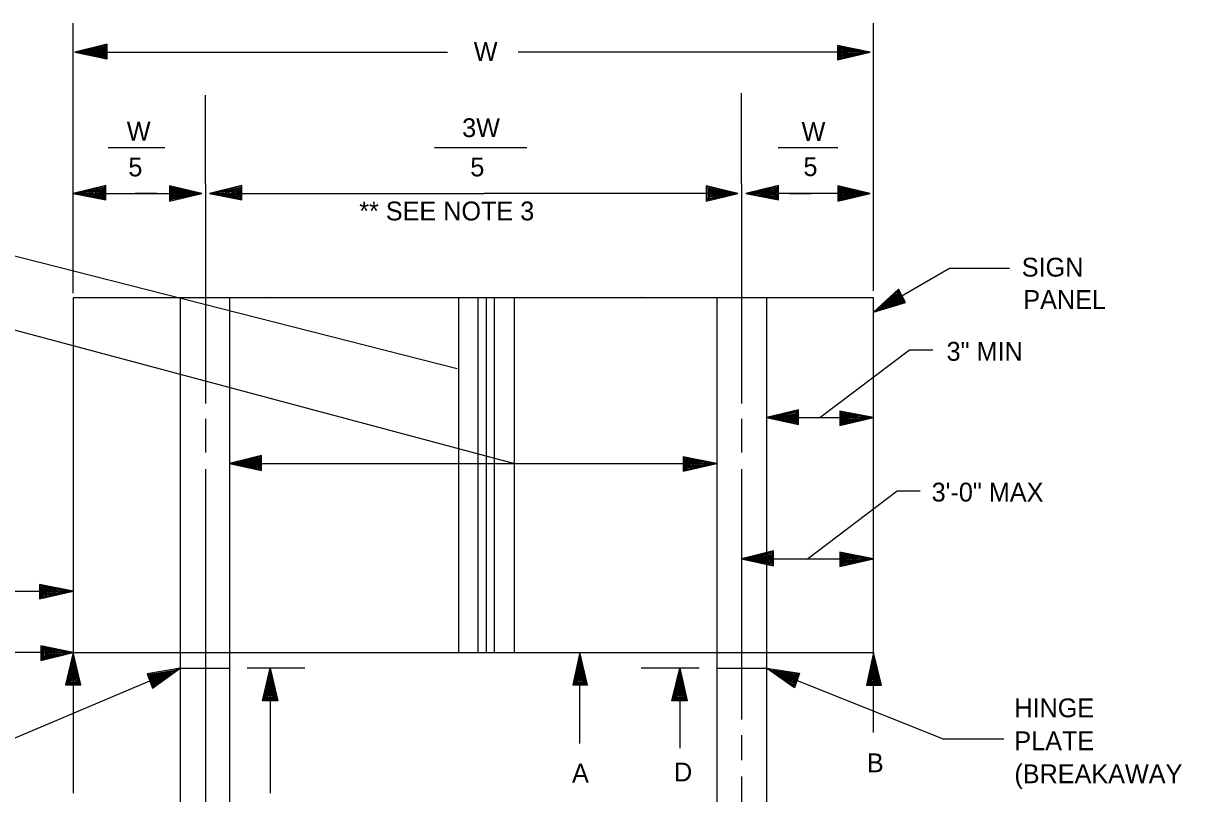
# Model space of a CAD drawing. Extents: x 139.2 to 146.5, y 202.4 to 212.6.
# Drawn here: x 142.714 to 146.404, y 210.118 to 212.573 of the extents above; entities that cross this region are included whole.
import ezdxf

# ---------------------------------------------------------------- set-up
doc = ezdxf.new("R2010")
doc.units = 0
for name, color, linetype in [('DETL-DIMS', 7, 'Continuous'), ('DETL-NOTE', 7, 'Continuous'), ('TTLB-TEXT', 7, 'Continuous')]:
    doc.layers.add(name, color=color, linetype=linetype)

msp = doc.modelspace()

# ---------------------------------------------------------------- linework, layer by layer
at = {"layer": 'DETL-DIMS'}
for p, q in [((142.873, 211.713), (142.873, 212.5728)), ((145.422, 211.7206), (145.422, 212.5728)), ((142.878, 212.4808), (144.065, 212.4808)), ((145.411, 212.4808), (144.29, 212.4808)), ((143.295, 212.0608), (143.295, 212.3438)), ((145.002, 212.0608), (145.002, 212.3498)), ((142.873, 212.0308), (143.283, 212.0308)), ((143.14, 212.0308), (143.071, 212.0308)), ((143.295, 212.0608), (143.295, 211.361)), ((143.307, 212.0308), (144.182, 212.0308)), ((144.99, 212.0308), (144.182, 212.0308)), ((145.002, 212.0608), (145.002, 211.361)), ((145.411, 212.0308), (145.015, 212.0308)), ((145.155, 212.0308), (145.224, 212.0308)), ((145.422, 211.6521), (145.6644, 211.7924)), ((145.6644, 211.7924), (145.8554, 211.7924)), ((145.2515, 211.3164), (145.5364, 211.5328)), ((145.5364, 211.5328), (145.6105, 211.5328)), ((143.295, 211.313), (143.295, 211.205)), ((145.002, 211.313), (145.002, 211.205)), ((145.081, 211.3164), (145.422, 211.3164)), ((143.295, 211.152), (143.295, 209.857)), ((143.371, 211.1706), (144.923, 211.1706)), ((145.002, 211.152), (145.002, 210.355)), ((145.212, 210.8669), (145.4969, 211.0833)), ((145.4969, 211.0833), (145.571, 211.0833)), ((145.002, 210.8669), (145.422, 210.8669)), ((140.875, 210.764), (142.873, 210.764)), ((142.873, 210.568), (140.273, 210.568)), ((142.873, 210.568), (142.873, 210.12)), ((144.4864, 210.2787), (144.4864, 210.568)), ((145.422, 210.314), (145.422, 210.568)), ((143.214, 210.518), (142.5028, 210.2173)), ((143.6114, 210.518), (143.4274, 210.518)), ((143.5008, 210.518), (143.5008, 210.12)), ((144.8664, 210.518), (144.6824, 210.518)), ((144.8049, 210.518), (144.8049, 210.2637)), ((145.081, 210.518), (145.6457, 210.2927)), ((145.002, 210.305), (145.002, 210.225)), ((145.8367, 210.2927), (145.6457, 210.2927)), ((145.002, 210.173), (145.002, 209.805))]:
    msp.add_line(p, q, dxfattribs=at)
for points in [[(142.982, 212.5058), (142.878, 212.4808), (142.982, 212.4588), (142.982, 212.5058)], [(142.978, 212.5018), (142.889, 212.4808), (142.978, 212.4588), (142.978, 212.5018)], [(142.977, 212.4978), (142.898, 212.4808), (142.977, 212.4628), (142.977, 212.4978)], [(142.975, 212.4968), (142.908, 212.4808), (142.975, 212.4668), (142.975, 212.4968)], [(142.972, 212.4928), (142.919, 212.4808), (142.972, 212.4688), (142.972, 212.4928)], [(142.971, 212.4918), (142.927, 212.4808), (142.971, 212.4688), (142.971, 212.4918)], [(142.968, 212.4878), (142.938, 212.4808), (142.968, 212.4728), (142.968, 212.4878)], [(142.966, 212.4838), (142.947, 212.4808), (142.966, 212.4768), (142.966, 212.4838)], [(142.965, 212.4828), (142.957, 212.4808), (142.965, 212.4788), (142.965, 212.4828)], [(145.307, 212.4558), (145.411, 212.4808), (145.307, 212.5018), (145.307, 212.4558)], [(145.308, 212.4588), (145.401, 212.4808), (145.308, 212.5008), (145.308, 212.4588)], [(145.313, 212.4608), (145.39, 212.4808), (145.313, 212.4968), (145.313, 212.4608)], [(145.315, 212.4628), (145.38, 212.4788), (145.315, 212.4958), (145.315, 212.4628)], [(145.316, 212.4668), (145.371, 212.4788), (145.316, 212.4918), (145.316, 212.4668)], [(145.318, 212.4688), (145.36, 212.4788), (145.318, 212.4878), (145.318, 212.4688)], [(145.319, 212.4718), (145.352, 212.4788), (145.319, 212.4858), (145.319, 212.4718)], [(145.323, 212.4758), (145.341, 212.4788), (145.323, 212.4838), (145.323, 212.4758)], [(145.325, 212.4768), (145.331, 212.4788), (145.325, 212.4808), (145.325, 212.4768)], [(144.0957, 211.472), (141.6601, 212.0915), (141.5263, 212.0915)], [(142.977, 212.0558), (142.873, 212.0308), (142.977, 212.0098), (142.977, 212.0558)], [(142.975, 212.0548), (142.883, 212.0308), (142.975, 212.0118), (142.975, 212.0548)], [(142.972, 212.0498), (142.894, 212.0308), (142.972, 212.0148), (142.972, 212.0498)], [(142.971, 212.0488), (142.905, 212.0328), (142.971, 212.0158), (142.971, 212.0488)], [(142.968, 212.0448), (142.913, 212.0328), (142.968, 212.0198), (142.968, 212.0448)], [(142.966, 212.0408), (142.923, 212.0328), (142.966, 212.0238), (142.966, 212.0408)], [(142.965, 212.0398), (142.932, 212.0328), (142.965, 212.0248), (142.965, 212.0398)], [(142.961, 212.0358), (142.943, 212.0328), (142.961, 212.0278), (142.961, 212.0358)], [(142.958, 212.0348), (142.953, 212.0328), (142.958, 212.0308), (142.958, 212.0348)], [(143.18, 212.0058), (143.283, 212.0308), (143.18, 212.0548), (143.18, 212.0058)], [(143.18, 212.0098), (143.273, 212.0308), (143.18, 212.0528), (143.18, 212.0098)], [(143.183, 212.0138), (143.263, 212.0308), (143.183, 212.0488), (143.183, 212.0138)], [(143.186, 212.0148), (143.252, 212.0308), (143.186, 212.0448), (143.186, 212.0148)], [(143.188, 212.0188), (143.243, 212.0308), (143.188, 212.0438), (143.188, 212.0188)], [(143.19, 212.0198), (143.232, 212.0308), (143.19, 212.0408), (143.19, 212.0198)], [(143.191, 212.0238), (143.223, 212.0308), (143.191, 212.0388), (143.191, 212.0238)], [(143.194, 212.0278), (143.213, 212.0308), (143.194, 212.0348), (143.194, 212.0278)], [(143.197, 212.0298), (143.202, 212.0308), (143.197, 212.0328), (143.197, 212.0298)], [(143.41, 212.0558), (143.307, 212.0308), (143.41, 212.0098), (143.41, 212.0558)], [(143.41, 212.0548), (143.316, 212.0308), (143.41, 212.0118), (143.41, 212.0548)], [(143.408, 212.0498), (143.327, 212.0308), (143.408, 212.0148), (143.408, 212.0498)], [(143.405, 212.0488), (143.336, 212.0328), (143.405, 212.0158), (143.405, 212.0488)], [(143.401, 212.0448), (143.347, 212.0328), (143.401, 212.0198), (143.401, 212.0448)], [(143.4, 212.0408), (143.357, 212.0328), (143.4, 212.0238), (143.4, 212.0408)], [(143.396, 212.0398), (143.366, 212.0328), (143.396, 212.0248), (143.396, 212.0398)], [(143.395, 212.0358), (143.377, 212.0328), (143.395, 212.0278), (143.395, 212.0358)], [(143.394, 212.0348), (143.385, 212.0328), (143.394, 212.0308), (143.394, 212.0348)], [(144.889, 212.0058), (144.99, 212.0308), (144.889, 212.0548), (144.889, 212.0058)], [(144.89, 212.0098), (144.982, 212.0308), (144.89, 212.0528), (144.89, 212.0098)], [(144.89, 212.0138), (144.971, 212.0308), (144.89, 212.0488), (144.89, 212.0138)], [(144.895, 212.0148), (144.963, 212.0308), (144.895, 212.0448), (144.895, 212.0148)], [(144.896, 212.0188), (144.951, 212.0308), (144.896, 212.0438), (144.896, 212.0188)], [(144.899, 212.0198), (144.94, 212.0308), (144.899, 212.0408), (144.899, 212.0198)], [(144.901, 212.0238), (144.932, 212.0308), (144.901, 212.0388), (144.901, 212.0238)], [(144.905, 212.0278), (144.921, 212.0308), (144.905, 212.0348), (144.905, 212.0278)], [(144.905, 212.0298), (144.913, 212.0308), (144.905, 212.0328), (144.905, 212.0298)], [(145.12, 212.0558), (145.015, 212.0308), (145.12, 212.0098), (145.12, 212.0558)], [(145.118, 212.0548), (145.026, 212.0308), (145.118, 212.0118), (145.118, 212.0548)], [(145.115, 212.0498), (145.036, 212.0308), (145.115, 212.0148), (145.115, 212.0498)], [(145.113, 212.0488), (145.047, 212.0328), (145.113, 212.0158), (145.113, 212.0488)], [(145.11, 212.0448), (145.056, 212.0328), (145.11, 212.0198), (145.11, 212.0448)], [(145.11, 212.0408), (145.066, 212.0328), (145.11, 212.0238), (145.11, 212.0408)], [(145.107, 212.0398), (145.076, 212.0328), (145.107, 212.0248), (145.107, 212.0398)], [(145.103, 212.0358), (145.086, 212.0328), (145.103, 212.0278), (145.103, 212.0358)], [(145.102, 212.0348), (145.097, 212.0328), (145.102, 212.0308), (145.102, 212.0348)], [(145.308, 212.0058), (145.411, 212.0308), (145.308, 212.0548), (145.308, 212.0058)], [(145.311, 212.0098), (145.402, 212.0308), (145.311, 212.0528), (145.311, 212.0098)], [(145.313, 212.0138), (145.391, 212.0308), (145.313, 212.0488), (145.313, 212.0138)], [(145.316, 212.0148), (145.383, 212.0308), (145.316, 212.0448), (145.316, 212.0148)], [(145.318, 212.0188), (145.373, 212.0308), (145.318, 212.0438), (145.318, 212.0188)], [(145.319, 212.0198), (145.363, 212.0308), (145.319, 212.0408), (145.319, 212.0198)], [(145.323, 212.0238), (145.353, 212.0308), (145.323, 212.0388), (145.323, 212.0238)], [(145.325, 212.0278), (145.343, 212.0308), (145.325, 212.0348), (145.325, 212.0278)], [(145.327, 212.0298), (145.333, 212.0308), (145.327, 212.0328), (145.327, 212.0298)], [(144.2793, 211.1696), (141.7634, 211.8414), (141.6646, 211.8414)], [(145.5013, 211.7261), (145.422, 211.6521), (145.5242, 211.6829), (145.5013, 211.7261)], [(145.5004, 211.7221), (145.431, 211.6587), (145.5206, 211.6848), (145.5004, 211.7221)], [(145.5, 211.7212), (145.4391, 211.6636), (145.5171, 211.6866), (145.5, 211.7212)], [(145.499, 211.7171), (145.4498, 211.6693), (145.5153, 211.6875), (145.499, 211.7171)], [(145.4994, 211.7113), (145.4575, 211.6732), (145.5117, 211.6893), (145.4994, 211.7113)], [(145.4985, 211.7095), (145.4656, 211.6781), (145.5082, 211.6911), (145.4985, 211.7095)], [(145.498, 211.7064), (145.4741, 211.6838), (145.5046, 211.6929), (145.498, 211.7064)], [(145.4966, 211.7015), (145.4831, 211.6882), (145.5015, 211.6934), (145.4966, 211.7015)], [(145.4948, 211.698), (145.4912, 211.6931), (145.4979, 211.6952), (145.4948, 211.698)], [(145.183, 211.3414), (145.081, 211.3164), (145.183, 211.2944), (145.183, 211.3414)], [(145.182, 211.3384), (145.093, 211.3164), (145.182, 211.2954), (145.182, 211.3384)], [(145.181, 211.3344), (145.099, 211.3164), (145.181, 211.2994), (145.181, 211.3344)], [(145.178, 211.3334), (145.11, 211.3164), (145.178, 211.3034), (145.178, 211.3334)], [(145.177, 211.3284), (145.119, 211.3164), (145.177, 211.3044), (145.177, 211.3284)], [(145.173, 211.3284), (145.13, 211.3164), (145.173, 211.3054), (145.173, 211.3284)], [(145.315, 211.2914), (145.422, 211.3164), (145.315, 211.3374), (145.315, 211.2914)], [(145.319, 211.2924), (145.411, 211.3164), (145.319, 211.3344), (145.319, 211.2924)], [(145.323, 211.2964), (145.399, 211.3164), (145.323, 211.3304), (145.323, 211.2964)], [(145.324, 211.2974), (145.389, 211.3134), (145.324, 211.3294), (145.324, 211.2974)], [(145.324, 211.3014), (145.38, 211.3134), (145.324, 211.3264), (145.324, 211.3014)], [(145.172, 211.3244), (145.141, 211.3164), (145.172, 211.3094), (145.172, 211.3244)], [(145.168, 211.3204), (145.152, 211.3164), (145.168, 211.3134), (145.168, 211.3204)], [(145.166, 211.3184), (145.161, 211.3164), (145.166, 211.3144), (145.166, 211.3184)], [(145.328, 211.3054), (145.369, 211.3134), (145.328, 211.3224), (145.328, 211.3054)], [(145.329, 211.3074), (145.36, 211.3134), (145.329, 211.3204), (145.329, 211.3074)], [(145.333, 211.3094), (145.349, 211.3134), (145.333, 211.3184), (145.333, 211.3094)], [(145.334, 211.3124), (145.339, 211.3134), (145.334, 211.3164), (145.334, 211.3124)], [(143.473, 211.1956), (143.371, 211.1706), (143.473, 211.1486), (143.473, 211.1956)], [(143.472, 211.1926), (143.383, 211.1706), (143.472, 211.1496), (143.472, 211.1926)], [(143.471, 211.1886), (143.389, 211.1706), (143.471, 211.1536), (143.471, 211.1886)], [(143.468, 211.1876), (143.4, 211.1706), (143.468, 211.1576), (143.468, 211.1876)], [(143.467, 211.1826), (143.409, 211.1706), (143.467, 211.1586), (143.467, 211.1826)], [(143.463, 211.1826), (143.42, 211.1706), (143.463, 211.1596), (143.463, 211.1826)], [(143.462, 211.1786), (143.431, 211.1706), (143.462, 211.1636), (143.462, 211.1786)], [(144.816, 211.1456), (144.923, 211.1706), (144.816, 211.1916), (144.816, 211.1456)], [(144.82, 211.1466), (144.912, 211.1706), (144.82, 211.1886), (144.82, 211.1466)], [(144.824, 211.1506), (144.9, 211.1706), (144.824, 211.1846), (144.824, 211.1506)], [(144.825, 211.1516), (144.89, 211.1676), (144.825, 211.1836), (144.825, 211.1516)], [(144.825, 211.1556), (144.881, 211.1676), (144.825, 211.1806), (144.825, 211.1556)], [(143.458, 211.1746), (143.442, 211.1706), (143.458, 211.1676), (143.458, 211.1746)], [(143.456, 211.1726), (143.451, 211.1706), (143.456, 211.1686), (143.456, 211.1726)], [(144.829, 211.1596), (144.87, 211.1676), (144.829, 211.1766), (144.829, 211.1596)], [(144.83, 211.1616), (144.861, 211.1676), (144.83, 211.1746), (144.83, 211.1616)], [(144.834, 211.1636), (144.85, 211.1676), (144.834, 211.1726), (144.834, 211.1636)], [(144.835, 211.1666), (144.84, 211.1676), (144.835, 211.1706), (144.835, 211.1666)], [(145.104, 210.8919), (145.002, 210.8669), (145.104, 210.8449), (145.104, 210.8919)], [(145.103, 210.8889), (145.014, 210.8669), (145.103, 210.8459), (145.103, 210.8889)], [(145.102, 210.8849), (145.02, 210.8669), (145.102, 210.8499), (145.102, 210.8849)], [(145.099, 210.8839), (145.031, 210.8669), (145.099, 210.8539), (145.099, 210.8839)], [(145.315, 210.8419), (145.422, 210.8669), (145.315, 210.8879), (145.315, 210.8419)], [(145.319, 210.8429), (145.411, 210.8669), (145.319, 210.8849), (145.319, 210.8429)], [(145.098, 210.8789), (145.04, 210.8669), (145.098, 210.8549), (145.098, 210.8789)], [(145.094, 210.8789), (145.051, 210.8669), (145.094, 210.8559), (145.094, 210.8789)], [(145.093, 210.8749), (145.062, 210.8669), (145.093, 210.8599), (145.093, 210.8749)], [(145.089, 210.8709), (145.073, 210.8669), (145.089, 210.8639), (145.089, 210.8709)], [(145.087, 210.8689), (145.082, 210.8669), (145.087, 210.8649), (145.087, 210.8689)], [(145.323, 210.8469), (145.399, 210.8669), (145.323, 210.8809), (145.323, 210.8469)], [(145.324, 210.8479), (145.389, 210.8639), (145.324, 210.8799), (145.324, 210.8479)], [(145.324, 210.8519), (145.38, 210.8639), (145.324, 210.8769), (145.324, 210.8519)], [(145.328, 210.8559), (145.369, 210.8639), (145.328, 210.8729), (145.328, 210.8559)], [(145.329, 210.8579), (145.36, 210.8639), (145.329, 210.8709), (145.329, 210.8579)], [(145.333, 210.8599), (145.349, 210.8639), (145.333, 210.8689), (145.333, 210.8599)], [(145.334, 210.8629), (145.339, 210.8639), (145.334, 210.8669), (145.334, 210.8629)], [(142.766, 210.739), (142.873, 210.764), (142.766, 210.785), (142.766, 210.739)], [(142.77, 210.74), (142.862, 210.764), (142.77, 210.782), (142.77, 210.74)], [(142.774, 210.744), (142.85, 210.764), (142.774, 210.778), (142.774, 210.744)], [(142.775, 210.745), (142.84, 210.761), (142.775, 210.777), (142.775, 210.745)], [(142.775, 210.749), (142.831, 210.761), (142.775, 210.774), (142.775, 210.749)], [(142.779, 210.753), (142.82, 210.761), (142.779, 210.77), (142.779, 210.753)], [(142.78, 210.755), (142.811, 210.761), (142.78, 210.768), (142.78, 210.755)], [(142.784, 210.757), (142.8, 210.761), (142.784, 210.766), (142.784, 210.757)], [(142.785, 210.76), (142.79, 210.761), (142.785, 210.764), (142.785, 210.76)], [(142.77, 210.543), (142.873, 210.568), (142.77, 210.59), (142.77, 210.543)], [(142.771, 210.546), (142.864, 210.568), (142.771, 210.588), (142.771, 210.546)], [(142.774, 210.548), (142.853, 210.568), (142.774, 210.585), (142.774, 210.548)], [(142.777, 210.551), (142.844, 210.566), (142.777, 210.582), (142.777, 210.551)], [(142.78, 210.555), (142.833, 210.566), (142.78, 210.58), (142.78, 210.555)], [(142.78, 210.557), (142.823, 210.566), (142.78, 210.576), (142.78, 210.557)], [(142.785, 210.56), (142.815, 210.566), (142.785, 210.574), (142.785, 210.56)], [(142.785, 210.563), (142.805, 210.566), (142.785, 210.572), (142.785, 210.563)], [(142.789, 210.565), (142.795, 210.566), (142.789, 210.568), (142.789, 210.565)], [(142.898, 210.465), (142.873, 210.568), (142.849, 210.465), (142.898, 210.465)], [(142.894, 210.466), (142.873, 210.558), (142.853, 210.466), (142.894, 210.466)], [(144.5114, 210.465), (144.4864, 210.568), (144.4644, 210.465), (144.5114, 210.465)], [(144.5084, 210.466), (144.4864, 210.558), (144.4664, 210.466), (144.5084, 210.466)], [(145.447, 210.464), (145.422, 210.568), (145.4, 210.464), (145.447, 210.464)], [(145.444, 210.465), (145.422, 210.557), (145.402, 210.465), (145.444, 210.465)], [(142.891, 210.469), (142.873, 210.548), (142.855, 210.469), (142.891, 210.469)], [(142.889, 210.472), (142.873, 210.539), (142.858, 210.472), (142.889, 210.472)], [(142.888, 210.474), (142.873, 210.528), (142.863, 210.474), (142.888, 210.474)], [(142.883, 210.475), (142.873, 210.518), (142.864, 210.475), (142.883, 210.475)], [(143.1261, 210.4544), (143.214, 210.518), (143.1087, 210.5), (143.1261, 210.4544)], [(143.4758, 210.415), (143.5008, 210.518), (143.5248, 210.415), (143.4758, 210.415)], [(144.5064, 210.469), (144.4864, 210.548), (144.4694, 210.469), (144.5064, 210.469)], [(144.5034, 210.472), (144.4874, 210.539), (144.4734, 210.472), (144.5034, 210.472)], [(144.4994, 210.474), (144.4874, 210.528), (144.4744, 210.474), (144.4994, 210.474)], [(144.4964, 210.475), (144.4874, 210.518), (144.4784, 210.475), (144.4964, 210.475)], [(144.7799, 210.415), (144.8049, 210.518), (144.8289, 210.415), (144.7799, 210.415)], [(145.1703, 210.4564), (145.081, 210.518), (145.1867, 210.5024), (145.1703, 210.4564)], [(145.441, 210.469), (145.422, 210.547), (145.405, 210.469), (145.441, 210.469)], [(145.438, 210.472), (145.422, 210.536), (145.408, 210.472), (145.438, 210.472)], [(145.436, 210.473), (145.422, 210.527), (145.411, 210.473), (145.436, 210.473)], [(145.432, 210.474), (145.422, 210.516), (145.413, 210.474), (145.432, 210.474)], [(142.88, 210.48), (142.873, 210.51), (142.865, 210.48), (142.88, 210.48)], [(142.878, 210.481), (142.873, 210.499), (142.869, 210.481), (142.878, 210.481)], [(142.874, 210.482), (142.873, 210.49), (142.873, 210.482), (142.874, 210.482)], [(143.1275, 210.4582), (143.2042, 210.5125), (143.112, 210.4977), (143.1275, 210.4582)], [(143.1281, 210.4591), (143.1956, 210.5087), (143.1154, 210.4955), (143.1281, 210.4591)], [(143.1295, 210.4629), (143.1842, 210.5044), (143.117, 210.4944), (143.1295, 210.4629)], [(143.1298, 210.4687), (143.1761, 210.5014), (143.1203, 210.4921), (143.1298, 210.4687)], [(143.131, 210.4704), (143.1675, 210.4976), (143.1236, 210.4899), (143.131, 210.4704)], [(143.1318, 210.4734), (143.1583, 210.4929), (143.1269, 210.4876), (143.1318, 210.4734)], [(143.1338, 210.4781), (143.1489, 210.4897), (143.13, 210.4868), (143.1338, 210.4781)], [(143.136, 210.4815), (143.1402, 210.4859), (143.1333, 210.4845), (143.136, 210.4815)], [(143.4798, 210.416), (143.5008, 210.508), (143.5208, 210.416), (143.4798, 210.416)], [(143.4828, 210.419), (143.5008, 210.498), (143.5188, 210.419), (143.4828, 210.419)], [(143.4848, 210.422), (143.5008, 210.489), (143.5158, 210.422), (143.4848, 210.422)], [(143.4858, 210.424), (143.5008, 210.478), (143.5108, 210.424), (143.4858, 210.424)], [(144.4944, 210.48), (144.4874, 210.51), (144.4814, 210.48), (144.4944, 210.48)], [(144.4914, 210.481), (144.4874, 210.499), (144.4834, 210.481), (144.4914, 210.481)], [(144.4894, 210.482), (144.4874, 210.49), (144.4864, 210.482), (144.4894, 210.482)], [(144.7839, 210.416), (144.8049, 210.508), (144.8249, 210.416), (144.7839, 210.416)], [(144.7869, 210.419), (144.8049, 210.498), (144.8229, 210.419), (144.7869, 210.419)], [(144.7889, 210.422), (144.8049, 210.489), (144.8199, 210.422), (144.7889, 210.422)], [(144.7899, 210.424), (144.8049, 210.478), (144.8149, 210.424), (144.7899, 210.424)], [(145.1688, 210.4603), (145.0909, 210.5128), (145.1834, 210.5001), (145.1688, 210.4603)], [(145.1682, 210.4611), (145.0996, 210.5091), (145.1801, 210.4978), (145.1682, 210.4611)], [(145.1667, 210.4649), (145.1111, 210.5051), (145.1785, 210.4966), (145.1667, 210.4649)], [(145.1663, 210.4707), (145.1192, 210.5023), (145.1753, 210.4943), (145.1663, 210.4707)], [(145.1651, 210.4724), (145.1279, 210.4987), (145.172, 210.492), (145.1651, 210.4724)], [(145.1642, 210.4754), (145.1372, 210.4942), (145.1687, 210.4897), (145.1642, 210.4754)], [(145.1621, 210.48), (145.1468, 210.4912), (145.1657, 210.4887), (145.1621, 210.48)], [(145.1598, 210.4833), (145.1555, 210.4876), (145.1625, 210.4864), (145.1598, 210.4833)], [(145.43, 210.476), (145.422, 210.507), (145.415, 210.476), (145.43, 210.476)], [(145.427, 210.48), (145.422, 210.497), (145.42, 210.48), (145.427, 210.48)], [(145.425, 210.482), (145.422, 210.486), (145.422, 210.482), (145.425, 210.482)], [(143.4908, 210.425), (143.5008, 210.468), (143.5098, 210.425), (143.4908, 210.425)], [(143.4938, 210.43), (143.5008, 210.46), (143.5088, 210.43), (143.4938, 210.43)], [(143.4958, 210.431), (143.5008, 210.449), (143.5048, 210.431), (143.4958, 210.431)], [(143.4998, 210.432), (143.5008, 210.44), (143.5008, 210.432), (143.4998, 210.432)], [(144.7949, 210.425), (144.8049, 210.468), (144.8139, 210.425), (144.7949, 210.425)], [(144.7979, 210.43), (144.8049, 210.46), (144.8129, 210.43), (144.7979, 210.43)], [(144.7999, 210.431), (144.8049, 210.449), (144.8089, 210.431), (144.7999, 210.431)], [(144.8039, 210.432), (144.8049, 210.44), (144.8049, 210.432), (144.8039, 210.432)]]:
    msp.add_lwpolyline(points, dxfattribs=at)
at = {"layer": 'DETL-NOTE'}
for p, q in [((142.985, 212.1768), (143.165, 212.1768)), ((144.024, 212.1768), (144.318, 212.1768)), ((145.118, 212.1768), (145.308, 212.1768))]:
    msp.add_line(p, q, dxfattribs=at)
at = {"layer": 'TTLB-TEXT'}
for p, q in [((145.422, 211.698), (142.873, 211.698)), ((142.873, 211.698), (142.873, 210.568)), ((143.214, 211.698), (143.214, 210.568)), ((143.371, 211.698), (143.371, 210.568)), ((143.49, 211.702), (143.49, 211.702)), ((144.1, 211.698), (144.1, 210.568)), ((144.162, 211.698), (144.162, 210.568)), ((144.188, 211.698), (144.188, 210.568)), ((144.214, 211.698), (144.214, 210.568)), ((144.278, 211.698), (144.278, 210.568)), ((144.68, 211.702), (144.68, 211.702)), ((144.69, 211.702), (144.69, 211.702)), ((144.923, 211.698), (144.923, 210.568)), ((145.081, 211.698), (145.081, 210.568)), ((145.422, 210.568), (145.422, 211.698)), ((142.873, 210.568), (145.422, 210.568)), ((143.214, 210.568), (143.214, 209.41)), ((143.371, 210.568), (143.371, 209.41)), ((144.923, 210.568), (144.923, 209.81)), ((145.081, 210.568), (145.081, 209.81)), ((143.214, 210.518), (143.371, 210.518)), ((144.923, 210.518), (145.081, 210.518))]:
    msp.add_line(p, q, dxfattribs=at)

# ---------------------------------------------------------------- texts
at = {"layer": 'DETL-NOTE'}
for s, p in [('W', (144.149, 212.4528)), ('W', (143.044, 212.1988)), ('3W', (144.112, 212.2098)), ('W', (145.193, 212.1978)), ('5', (143.049, 212.0848)), ('5', (144.138, 212.0848)), ('5', (145.199, 212.0858)), ('** SEE NOTE 3', (143.7842, 211.9446)), ('SIGN', (145.8942, 211.7656)), ('PANEL', (145.8992, 211.6626)), ('3" MIN', (145.6548, 211.4976)), ('3\'-0" MAX', (145.6072, 211.0492)), ('HINGE', (145.8707, 210.3621)), ('PLATE', (145.8707, 210.2571)), ('D', (144.7868, 210.1579)), ('B', (145.401, 210.187)), ('A', (144.462, 210.1543)), ('(BREAKAWAY', (145.8707, 210.1521))]:
    msp.add_text(s, height=0.06, dxfattribs=at).set_placement(p)

doc.saveas('drawing.dxf')
